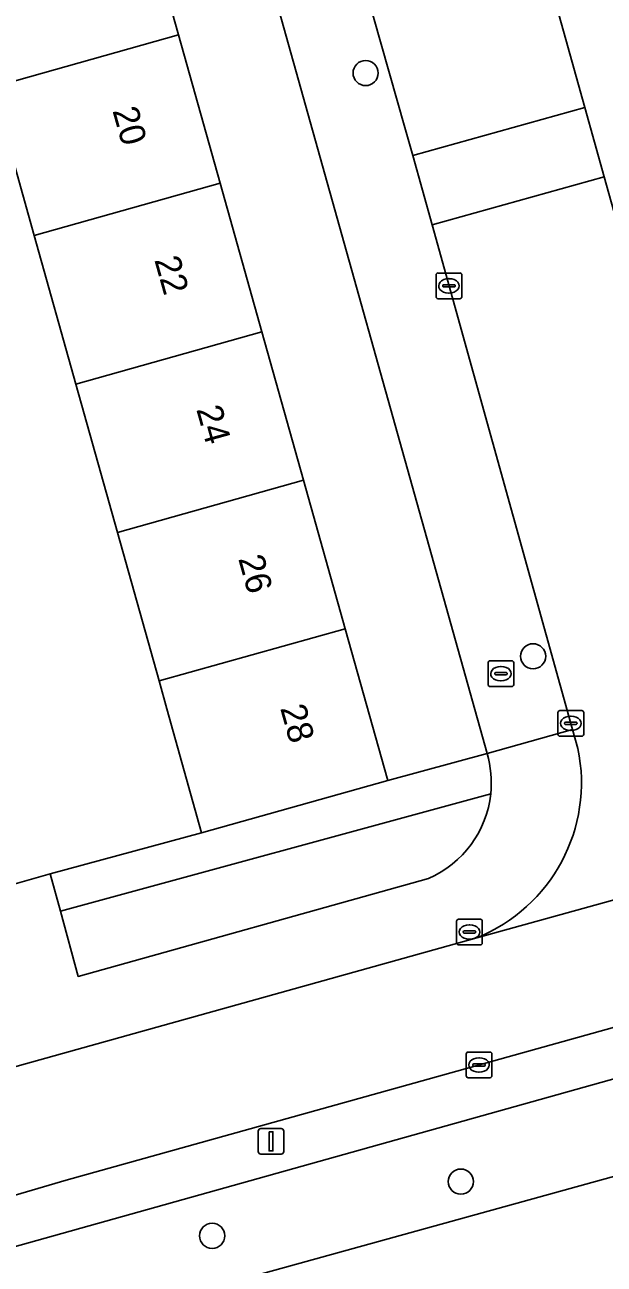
# Model space of a CAD drawing. Extents: x 159053 to 160042, y 380449 to 381423.
# Drawn here: x 159211.21 to 159233.77, y 380913.55 to 380961.78 of the extents above; entities that cross this region are included whole.
import ezdxf

# ---------------------------------------------------------------- set-up
doc = ezdxf.new("R2010")
doc.units = 0
for name, color, linetype in [('IMGEO_Boom', 7, 'Continuous'), ('IMGEO_Brandkraan', 7, 'Continuous'), ('IMGEO_Erf', 7, 'Continuous'), ('IMGEO_Groenvoorziening', 7, 'Continuous'), ('IMGEO_Hek', 7, 'Continuous'), ('IMGEO_Kolk', 7, 'Continuous'), ('IMGEO_Lichtmast', 7, 'Continuous'), ('IMGEO_Pand', 7, 'Continuous'), ('IMGEO_Pand_nummerreeks', 7, 'Continuous'), ('IMGEO_Rijbaan_lokaal_open', 7, 'Continuous'), ('IMGEO_Voetpad_open', 7, 'Continuous')]:
    doc.layers.add(name, color=color, linetype=linetype)

msp = doc.modelspace()

# ---------------------------------------------------------------- linework, layer by layer
at = {"layer": 'IMGEO_Boom'}
for centre in [(159224.483, 380959.896), (159231.002, 380937.204), (159228.189, 380916.762), (159218.51, 380914.655)]:
    msp.add_circle(centre, 0.489, dxfattribs=at)
at = {"layer": 'IMGEO_Brandkraan'}
for p, q in [((159229.325, 380937.027), (159230.177, 380937.027)), ((159229.25, 380936.101), (159229.25, 380936.953)), ((159229.509, 380936.521), (159229.509, 380936.533)), ((159229.552, 380936.57), (159229.95, 380936.57)), ((159229.738, 380936.807), (159229.763, 380936.807)), ((159229.993, 380936.533), (159229.993, 380936.521)), ((159230.251, 380936.953), (159230.251, 380936.101)), ((159230.177, 380936.027), (159229.325, 380936.027)), ((159229.947, 380936.484), (159229.549, 380936.484)), ((159229.761, 380936.247), (159229.736, 380936.247))]:
    msp.add_line(p, q, dxfattribs=at)
for points in [[(159229.325, 380937.027), (159230.177, 380937.027)], [(159229.25, 380936.101), (159229.25, 380936.953)], [(159230.251, 380936.953), (159230.251, 380936.101)], [(159230.177, 380936.027), (159229.325, 380936.027)]]:
    msp.add_lwpolyline(points, dxfattribs=at)
for centre, radius, start, end in [((159229.327, 380936.951), 0.0765, 91.552, 178.448), ((159229.327, 380936.951), 0.0765, 91.552, 178.448), ((159230.175, 380936.951), 0.0765, 1.552, 88.448), ((159230.175, 380936.951), 0.0765, 1.552, 88.448), ((159229.549, 380936.53), 0.0403, 85.8775, 175.7526), ((159229.546, 380936.52), 0.0366, 178.938, 274.7102), ((159229.95, 380936.527), 0.043, 264.8664, 352.4533), ((159229.954, 380936.532), 0.0386, 1.7309, 96.639), ((159229.327, 380936.103), 0.0765, 181.552, 268.448), ((159229.327, 380936.103), 0.0765, 181.552, 268.448), ((159230.175, 380936.103), 0.0765, 271.552, 358.448), ((159230.175, 380936.103), 0.0765, 271.552, 358.448)]:
    msp.add_arc(centre, radius, start, end, dxfattribs=at)
for centre, major_axis, ratio, start_param, end_param in [((159229.737, 380936.527), (-0.387, 0.002), 0.722429, 4.712389, 7.853982), ((159229.762, 380936.527), (-0.39, 0.002), 0.717154, 1.570796, 4.712389)]:
    msp.add_ellipse(centre, major_axis=major_axis, ratio=ratio, start_param=start_param, end_param=end_param, dxfattribs=at)
at = {"layer": 'IMGEO_Erf'}
msp.add_lwpolyline([(159229.211, 380933.416), (159210.55, 381000), (159204.751, 381020.689), (159200.94, 381019.636), (159202.602, 381013.694), (159204.217, 381007.916), (159205.833, 381002.138), (159206.431, 381000), (159207.449, 380996.36), (159209.065, 380990.581), (159210.68, 380984.803), (159212.339, 380978.871), (159210.485, 380978.351), (159211.299, 380975.452), (159212.112, 380972.554), (159213.923, 380973.063), (159215.58, 380967.161), (159217.202, 380961.384), (159218.824, 380955.608), (159220.446, 380949.831), (159222.068, 380944.054), (159223.69, 380938.278), (159225.347, 380932.375)], close=True, dxfattribs=at)
msp.add_lwpolyline([(159195.335, 380967.948), (159197.819, 380958.771), (159201.916, 380959.921), (159202.651, 380957.3), (159203.425, 380954.542), (159199.328, 380953.392), (159201.029, 380947.242), (159205.017, 380948.362), (159205.762, 380945.71), (159206.559, 380942.871), (159202.571, 380941.751), (159206.725, 380927.174), (159206.931, 380927.233), (159207.189, 380927.306), (159212.208, 380928.733), (159218.1, 380930.34), (159216.748, 380935.154), (159216.442, 380936.244), (159214.82, 380942.021), (159213.198, 380947.797), (159211.576, 380953.574), (159209.955, 380959.35), (159208.333, 380965.127)], dxfattribs=at)
at = {"layer": 'IMGEO_Groenvoorziening'}
msp.add_lwpolyline([(159296.448, 380934.184), (159296.42, 380934.314), (159296.393, 380934.435), (159295.42, 380937.918), (159199.726, 380911.13), (159195.395, 380909.913), (159194.248, 380908.271), (159194.979, 380906.143)], close=True, dxfattribs=at)
for points in [[(159321.643, 380924.103), (159318.603, 380934.661), (159305.427, 380930.949), (159298.973, 380929.13), (159298.341, 380931.373), (159308.663, 380934.21), (159308.52, 380934.729), (159307.969, 380936.734), (159307.839, 380937.207), (159309.118, 380937.568), (159309.054, 380937.802), (159296.42, 380934.314), (159296.448, 380934.184), (159194.979, 380906.143), (159220.802, 380811.72), (159340.546, 380844.447), (159336.09, 380860.753), (159223.202, 380829.611), (159222.554, 380831.933), (159236.663, 380835.876), (159259.546, 380842.271), (159305.824, 380855.205), (159335.776, 380863.627), (159336.487, 380863.886)], [(159229.211, 380933.416), (159225.347, 380932.375), (159218.1, 380930.34), (159212.208, 380928.733), (159212.602, 380927.289), (159229.352, 380931.854)], [(159229.352, 380931.854), (159212.602, 380927.289), (159213.294, 380924.749), (159226.936, 380928.562)]]:
    msp.add_lwpolyline(points, dxfattribs=at)
for centre, radius, start, end in [((159225.334, 380932.279), 4.041, 353.9681, 16.348), ((159225.327, 380932.275), 4.047, 293.4266, 354.0235)]:
    msp.add_arc(centre, radius, start, end, dxfattribs=at)
at = {"layer": 'IMGEO_Hek'}
msp.add_lwpolyline([(159194.979, 380906.143), (159296.448, 380934.184)], dxfattribs=at)
at = {"layer": 'IMGEO_Kolk'}
for p, q in [((159227.226, 380951.191), (159227.226, 380952.043)), ((159227.301, 380952.117), (159228.153, 380952.117)), ((159228.227, 380952.043), (159228.227, 380951.191)), ((159227.485, 380951.611), (159227.485, 380951.623)), ((159227.923, 380951.574), (159227.525, 380951.574)), ((159227.528, 380951.66), (159227.926, 380951.66)), ((159227.714, 380951.897), (159227.739, 380951.897)), ((159227.969, 380951.623), (159227.969, 380951.611)), ((159228.153, 380951.117), (159227.301, 380951.117)), ((159227.737, 380951.337), (159227.712, 380951.337)), ((159232.045, 380935.093), (159232.897, 380935.093)), ((159231.97, 380934.167), (159231.97, 380935.019)), ((159232.229, 380934.587), (159232.229, 380934.599)), ((159232.272, 380934.636), (159232.67, 380934.636)), ((159232.458, 380934.873), (159232.483, 380934.873)), ((159232.713, 380934.599), (159232.713, 380934.587)), ((159232.971, 380935.019), (159232.971, 380934.167)), ((159232.897, 380934.093), (159232.045, 380934.093)), ((159232.667, 380934.55), (159232.269, 380934.55)), ((159232.481, 380934.313), (159232.456, 380934.313)), ((159228.024, 380926.048), (159228.024, 380926.9)), ((159228.099, 380926.974), (159228.951, 380926.974)), ((159229.025, 380926.9), (159229.025, 380926.048)), ((159228.283, 380926.468), (159228.283, 380926.48)), ((159228.721, 380926.431), (159228.323, 380926.431)), ((159228.326, 380926.517), (159228.724, 380926.517)), ((159228.512, 380926.754), (159228.537, 380926.754)), ((159228.767, 380926.48), (159228.767, 380926.468)), ((159228.951, 380925.974), (159228.099, 380925.974)), ((159228.535, 380926.194), (159228.51, 380926.194)), ((159228.396, 380920.876), (159228.396, 380921.728)), ((159228.471, 380921.802), (159229.323, 380921.802)), ((159228.884, 380921.582), (159228.909, 380921.582)), ((159229.397, 380921.728), (159229.397, 380920.876)), ((159228.655, 380921.296), (159228.655, 380921.308)), ((159229.093, 380921.259), (159228.695, 380921.259)), ((159228.698, 380921.345), (159229.096, 380921.345)), ((159229.139, 380921.308), (159229.139, 380921.296)), ((159229.323, 380920.802), (159228.471, 380920.802)), ((159228.907, 380921.022), (159228.882, 380921.022))]:
    msp.add_line(p, q, dxfattribs=at)
for points in [[(159227.226, 380951.191), (159227.226, 380952.043)], [(159227.301, 380952.117), (159228.153, 380952.117)], [(159228.227, 380952.043), (159228.227, 380951.191)], [(159228.153, 380951.117), (159227.301, 380951.117)], [(159232.045, 380935.093), (159232.897, 380935.093)], [(159231.97, 380934.167), (159231.97, 380935.019)], [(159232.971, 380935.019), (159232.971, 380934.167)], [(159232.897, 380934.093), (159232.045, 380934.093)], [(159228.024, 380926.048), (159228.024, 380926.9)], [(159228.099, 380926.974), (159228.951, 380926.974)], [(159229.025, 380926.9), (159229.025, 380926.048)], [(159228.951, 380925.974), (159228.099, 380925.974)], [(159228.396, 380920.876), (159228.396, 380921.728)], [(159228.471, 380921.802), (159229.323, 380921.802)], [(159229.397, 380921.728), (159229.397, 380920.876)], [(159229.323, 380920.802), (159228.471, 380920.802)]]:
    msp.add_lwpolyline(points, dxfattribs=at)
for centre, radius, start, end in [((159227.303, 380952.041), 0.0765, 91.552, 178.448), ((159227.303, 380952.041), 0.0765, 91.552, 178.448), ((159228.151, 380952.041), 0.0765, 1.552, 88.448), ((159228.151, 380952.041), 0.0765, 1.552, 88.448), ((159227.525, 380951.62), 0.0403, 85.8775, 175.7526), ((159227.522, 380951.61), 0.0366, 178.938, 274.7102), ((159227.926, 380951.617), 0.043, 264.8664, 352.4533), ((159227.93, 380951.622), 0.0386, 1.7309, 96.639), ((159227.303, 380951.193), 0.0765, 181.552, 268.448), ((159227.303, 380951.193), 0.0765, 181.552, 268.448), ((159228.151, 380951.193), 0.0765, 271.552, 358.448), ((159228.151, 380951.193), 0.0765, 271.552, 358.448), ((159232.047, 380935.017), 0.0765, 91.552, 178.448), ((159232.047, 380935.017), 0.0765, 91.552, 178.448), ((159232.895, 380935.017), 0.0765, 1.552, 88.448), ((159232.895, 380935.017), 0.0765, 1.552, 88.448), ((159232.269, 380934.596), 0.0403, 85.8775, 175.7526), ((159232.266, 380934.586), 0.0366, 178.938, 274.7102), ((159232.67, 380934.593), 0.043, 264.8664, 352.4533), ((159232.674, 380934.598), 0.0386, 1.7309, 96.639), ((159232.047, 380934.169), 0.0765, 181.552, 268.448), ((159232.047, 380934.169), 0.0765, 181.552, 268.448), ((159232.895, 380934.169), 0.0765, 271.552, 358.448), ((159232.895, 380934.169), 0.0765, 271.552, 358.448), ((159228.101, 380926.898), 0.0765, 91.552, 178.448), ((159228.101, 380926.898), 0.0765, 91.552, 178.448), ((159228.949, 380926.898), 0.0765, 1.552, 88.448), ((159228.949, 380926.898), 0.0765, 1.552, 88.448), ((159228.323, 380926.477), 0.0403, 85.8775, 175.7526), ((159228.32, 380926.467), 0.0366, 178.938, 274.7102), ((159228.724, 380926.474), 0.043, 264.8664, 352.4533), ((159228.728, 380926.479), 0.0386, 1.7309, 96.639), ((159228.101, 380926.05), 0.0765, 181.552, 268.448), ((159228.101, 380926.05), 0.0765, 181.552, 268.448), ((159228.949, 380926.05), 0.0765, 271.552, 358.448), ((159228.949, 380926.05), 0.0765, 271.552, 358.448), ((159228.473, 380921.726), 0.0765, 91.552, 178.448), ((159228.473, 380921.726), 0.0765, 91.552, 178.448), ((159229.321, 380921.726), 0.0765, 1.552, 88.448), ((159229.321, 380921.726), 0.0765, 1.552, 88.448), ((159228.695, 380921.305), 0.0403, 85.8775, 175.7526), ((159228.692, 380921.295), 0.0366, 178.938, 274.7102), ((159229.096, 380921.302), 0.043, 264.8664, 352.4533), ((159229.1, 380921.307), 0.0386, 1.7309, 96.639), ((159228.473, 380920.878), 0.0765, 181.552, 268.448), ((159228.473, 380920.878), 0.0765, 181.552, 268.448), ((159229.321, 380920.878), 0.0765, 271.552, 358.448), ((159229.321, 380920.878), 0.0765, 271.552, 358.448)]:
    msp.add_arc(centre, radius, start, end, dxfattribs=at)
for centre, major_axis, ratio, start_param, end_param in [((159227.713, 380951.617), (-0.387, 0.002), 0.722429, 4.712389, 7.853982), ((159227.738, 380951.617), (-0.39, 0.002), 0.717154, 1.570796, 4.712389), ((159232.457, 380934.593), (-0.387, 0.002), 0.722429, 4.712389, 7.853982), ((159232.482, 380934.593), (-0.39, 0.002), 0.717154, 1.570796, 4.712389), ((159228.511, 380926.474), (-0.387, 0.002), 0.722429, 4.712389, 7.853982), ((159228.536, 380926.474), (-0.39, 0.002), 0.717154, 1.570796, 4.712389), ((159228.883, 380921.302), (-0.387, 0.002), 0.722429, 4.712389, 7.853982), ((159228.908, 380921.302), (-0.39, 0.002), 0.717154, 1.570796, 4.712389)]:
    msp.add_ellipse(centre, major_axis=major_axis, ratio=ratio, start_param=start_param, end_param=end_param, dxfattribs=at)
at = {"layer": 'IMGEO_Lichtmast'}
for p, q in [((159220.304, 380917.93), (159220.304, 380918.73)), ((159220.304, 380918.73), (159220.304, 380917.93)), ((159220.404, 380918.83), (159221.194, 380918.83)), ((159221.194, 380918.83), (159220.404, 380918.83)), ((159221.294, 380918.73), (159221.294, 380917.93)), ((159221.294, 380917.93), (159221.294, 380918.73)), ((159221.194, 380917.83), (159220.404, 380917.83)), ((159220.404, 380917.83), (159221.194, 380917.83))]:
    msp.add_line(p, q, dxfattribs=at)
msp.add_lwpolyline([(159220.724, 380918.705), (159220.874, 380918.705), (159220.874, 380917.955), (159220.724, 380917.955), (159220.724, 380918.705)], dxfattribs=at)
for centre, start, end in [((159220.404, 380918.73), 90, 180), ((159220.404, 380918.73), 90, 180), ((159221.194, 380918.73), 0, 90), ((159221.194, 380918.73), 360, 90), ((159220.404, 380917.93), 180, 270), ((159220.404, 380917.93), 180, 270), ((159221.194, 380917.93), 270, 0), ((159221.194, 380917.93), 270, 0)]:
    msp.add_arc(centre, 0.1, start, end, dxfattribs=at)
at = {"layer": 'IMGEO_Pand'}
for points in [[(159215.58, 380967.161), (159208.333, 380965.127), (159209.955, 380959.35), (159217.202, 380961.384)], [(159217.202, 380961.384), (159209.955, 380959.35), (159211.576, 380953.574), (159218.824, 380955.608)], [(159213.198, 380947.797), (159220.446, 380949.831), (159218.824, 380955.608), (159211.576, 380953.574)], [(159222.068, 380944.054), (159220.446, 380949.831), (159213.198, 380947.797), (159214.82, 380942.021)], [(159222.068, 380944.054), (159214.82, 380942.021), (159216.442, 380936.244), (159223.69, 380938.278)], [(159223.69, 380938.278), (159216.442, 380936.244), (159216.748, 380935.154), (159218.1, 380930.34), (159225.347, 380932.375)]]:
    msp.add_lwpolyline(points, close=True, dxfattribs=at)
at = {"layer": 'IMGEO_Rijbaan_lokaal_open'}
for points in [[(159226.315, 380956.684), (159233.01, 380958.559), (159227.69, 380977.591), (159222.598, 380995.644), (159221.437, 381000), (159221.152, 381001.023), (159217.481, 381000), (159214.376, 380999.135), (159215.914, 380993.702), (159219.592, 380980.397), (159226.01, 380957.779)], [(159233.764, 380955.863), (159233.01, 380958.559), (159226.315, 380956.684), (159227.067, 380953.987)]]:
    msp.add_lwpolyline(points, close=True, dxfattribs=at)
for points in [[(159239.173, 380934.996), (159238.874, 380936.156), (159234.335, 380953.821), (159233.764, 380955.863), (159227.067, 380953.987), (159231.034, 380939.757), (159232.538, 380934.356), (159232.744, 380933.615)], [(159245.785, 380930.949), (159228.811, 380926.254), (159204.121, 380919.367), (159205.315, 380914.615), (159212.83, 380916.824), (159251.048, 380927.477)], [(159228.811, 380926.254), (159245.785, 380930.949)]]:
    msp.add_lwpolyline(points, dxfattribs=at)
msp.add_arc((159226.392, 380932.278), 6.491, 291.8774, 11.8912, dxfattribs=at)
at = {"layer": 'IMGEO_Voetpad_open'}
for points in [[(159217.284, 381024.142), (159216.867, 381025.644), (159214.295, 381024.942), (159219.206, 381008.024), (159220.402, 381003.72), (159221.152, 381001.023), (159221.437, 381000), (159222.598, 380995.644), (159227.69, 380977.591), (159233.01, 380958.559), (159233.764, 380955.863), (159234.335, 380953.821), (159238.874, 380936.156), (159241.698, 380936.943), (159224.043, 381000)], [(159208.001, 381021.538), (159204.751, 381020.689), (159210.55, 381000), (159229.211, 380933.416), (159232.538, 380934.356), (159231.034, 380939.757), (159227.067, 380953.987), (159226.315, 380956.684), (159226.01, 380957.779), (159219.592, 380980.397), (159215.914, 380993.702), (159214.376, 380999.135), (159214.131, 381000), (159213.62, 381001.831), (159212.955, 381004.209)]]:
    msp.add_lwpolyline(points, close=True, dxfattribs=at)
for points in [[(159309.441, 380943.822), (159291.177, 380938.669), (159273.09, 380933.625), (159270.392, 380932.872), (159251.048, 380927.477), (159212.83, 380916.824), (159205.315, 380914.615), (159202.625, 380913.824), (159202.183, 380913.694), (159193.225, 380911.241), (159191.928, 380910.886), (159183.581, 380908.568), (159183.081, 380908.43), (159184.215, 380904.409), (159186.407, 380905.035), (159191.171, 380906.353), (159191.665, 380904.574), (159194.248, 380908.271), (159195.395, 380909.913), (159199.726, 380911.13), (159295.42, 380937.918)], [(159232.744, 380933.615), (159232.538, 380934.356), (159229.211, 380933.416)], [(159226.936, 380928.562), (159213.294, 380924.749), (159212.602, 380927.289), (159212.208, 380928.733), (159207.189, 380927.306), (159208.373, 380923.373), (159207.997, 380923.268), (159207.633, 380923.166), (159206.511, 380927.113), (159205.498, 380926.825), (159205.89, 380925.371), (159206.564, 380922.867), (159191.052, 380918.531), (159186.01, 380917.122)], [(159186.773, 380914.618), (159201.414, 380918.639), (159204.121, 380919.367), (159228.811, 380926.254)]]:
    msp.add_lwpolyline(points, dxfattribs=at)
for centre, radius, start, end in [((159226.392, 380932.278), 6.491, 291.8774, 11.8912), ((159225.334, 380932.279), 4.041, 353.9681, 16.348), ((159225.327, 380932.275), 4.047, 293.4266, 354.0235)]:
    msp.add_arc(centre, radius, start, end, dxfattribs=at)

# ---------------------------------------------------------------- texts
at = {"layer": 'IMGEO_Pand_nummerreeks'}
for s, p in [('20', (159214.623, 380958.438)), ('22', (159216.253, 380952.631)), ('24', (159217.886, 380946.816)), ('26', (159219.518, 380941.003)), ('28', (159221.151, 380935.187))]:
    msp.add_text(s, height=1, rotation=285.6832, dxfattribs=at).set_placement(p)

doc.saveas('drawing.dxf')
